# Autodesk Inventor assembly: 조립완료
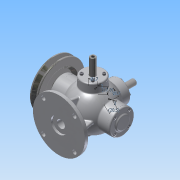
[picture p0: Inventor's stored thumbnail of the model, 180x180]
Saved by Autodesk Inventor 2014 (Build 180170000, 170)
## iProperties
Created: 2016-01
Part Number: 조립완료
Document SubType Name: Assembly
Designer: Administrator
Author: Administrator
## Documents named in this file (17)
- C:\Users\Administrator\Desktop\360108V1014\조립완료.iam
- C:\Users\Administrator\Desktop\360108V1014\본체.ipt
- C:\Users\Administrator\Desktop\360108V1014\앞커버.ipt
- C:\Users\Administrator\Desktop\360108V1014\뒤커버.ipt
- C:\Users\Administrator\Desktop\360108V1014\베어링- 6202.ipt
- C:\Users\Administrator\Desktop\360108V1014\축.ipt
- C:\Users\Administrator\Desktop\360108V1014\본체커버.ipt
- C:\Users\Administrator\Desktop\360108V1014\볼트 M4x0.7.ipt
- C:\Users\Administrator\Desktop\360108V1014\슬라이드.ipt
- C:\Users\Administrator\Desktop\360108V1014\키-4x4.ipt
- C:\Users\Administrator\Desktop\360108V1014\오일실.ipt
- C:\Users\Administrator\Desktop\360108V1014\슬라이드 커버.ipt
- C:\Users\Administrator\Desktop\360108V1014\V-벨트풀리.ipt
- C:\Users\Administrator\Desktop\360108V1014\너트-M8x1.ipt
- C:\Users\Administrator\Desktop\360108V1014\와셔 8x17.ipt
- C:\Users\Administrator\Desktop\360108V1014\가변스프링.ipt
- C:\Users\Administrator\Desktop\360108V1014\가변스프링2.ipt
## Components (20 placed, 4 different names)
1. M4x0.7x12:5
2. V-벨트풀리:1 — 플러쉬:1, 각도:2
3. 가변스프링:1
4. 가변스프링2:1
5. M4x0.7x12:1
6. M4x0.7x12:2
7. M4x0.7x12:3
8. M4x0.7x12:4
9. M4x0.7x12:6
10. M4x0.7x12:7
11. M4x0.7x12:8
12. M4x0.7x12:9
13. M4x0.7x12:10
14. M4x0.7x12:11
15. M4x0.7x12:12
16. M4x0.7x12:13
17. M4x0.7x12:14
18. M4x0.7x12:15
19. M4x0.7x12:16
20. M4x0.7x12:17
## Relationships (2: Flush 1, Angle 1)
- 플러쉬:1 [Flush]: V-벨트풀리:1
- 각도:2 [Angle]: V-벨트풀리:1
